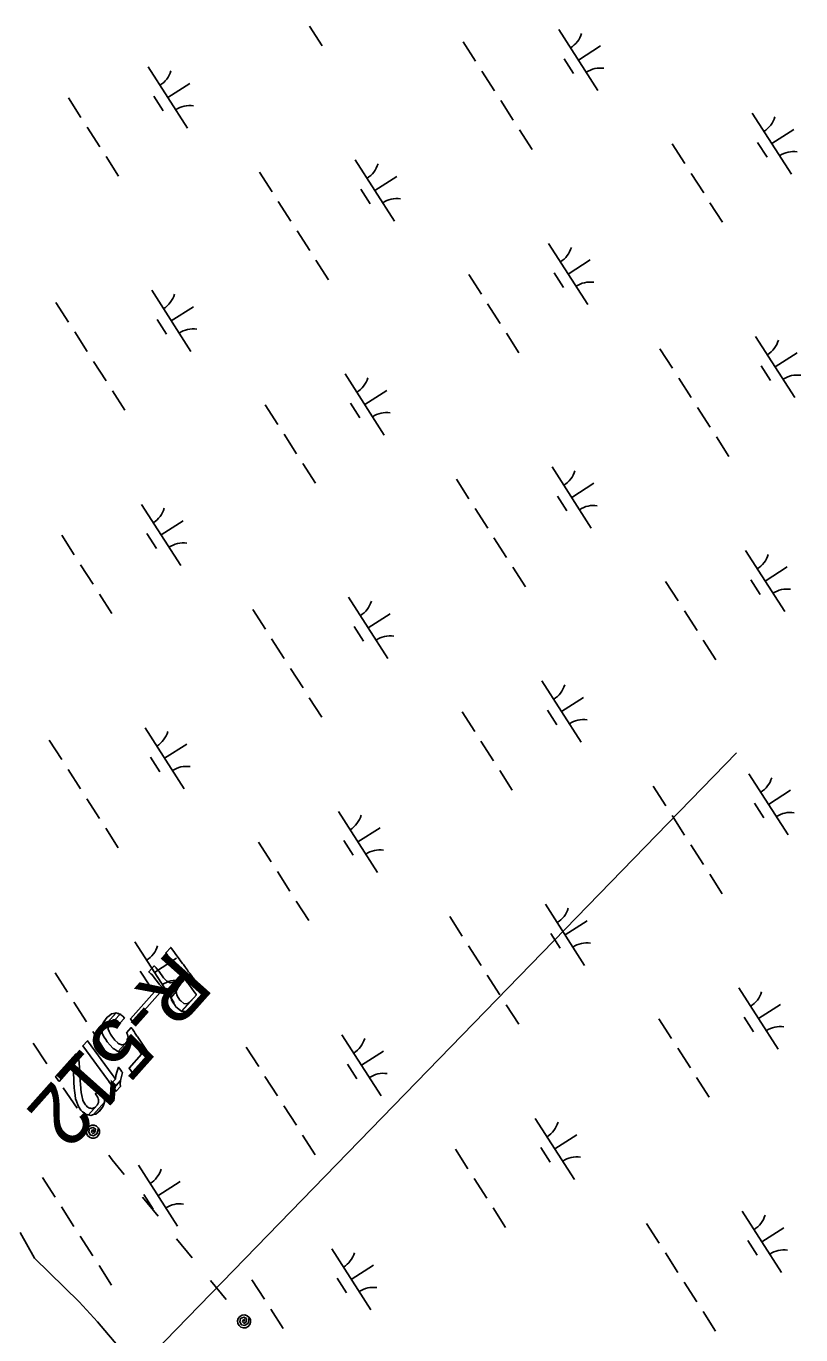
# Model space of a CAD drawing. Extents: x 3962991 to 3983549, y 181631 to 204078.
# Drawn here: x 3971703 to 3972236, y 196321 to 197222 of the extents above; entities that cross this region are included whole.
import ezdxf

# ---------------------------------------------------------------- set-up
doc = ezdxf.new("R2010")
doc.units = 0
for name, color, linetype in [('V-ANNO-MASK', 7, 'Continuous'), ('V-ANNO-MASK2', 7, 'Continuous'), ('V-RIVR-RANG-IDEN', 7, 'Continuous'), ('V-UTIL-LINE', 7, 'Continuous'), ('V-WETL-SWMP', 7, 'Continuous')]:
    doc.layers.add(name, color=color, linetype=linetype)

msp = doc.modelspace()

# ---------------------------------------------------------------- linework, layer by layer
at = {"layer": 'V-ANNO-MASK2'}
for points in [[(3971803.82, 196586.27), (3971802.63, 196587.89), (3971799.21, 196584.05), (3971800.4, 196582.43), (3971800.65, 196582.09), (3971801.86, 196580.45), (3971802.22, 196579.95), (3971805.42, 196575.6), (3971805.82, 196575.04), (3971807.31, 196573.01), (3971807.93, 196572.18), (3971808.91, 196570.84), (3971809.62, 196569.87), (3971809.84, 196569.57), (3971810.03, 196569.31), (3971800.66, 196558.81), (3971802.29, 196558.9), (3971804.9, 196560.35), (3971803.74, 196558.52), (3971802.64, 196555.42), (3971802.7, 196555.05), (3971812.46, 196566), (3971812.58, 196565.84), (3971813.21, 196564.98), (3971814.25, 196563.56), (3971814.59, 196563.11), (3971816.67, 196560.27), (3971817.22, 196559.52), (3971818.77, 196557.41), (3971819.91, 196555.87), (3971820.14, 196555.54), (3971820.14, 196555.55), (3971820.24, 196555.41), (3971820.28, 196555.34), (3971810.21, 196544.05), (3971813.84, 196543.83), (3971817.17, 196545.69), (3971820.25, 196548.88), (3971826.29, 196555.65), (3971826.18, 196555.8), (3971825.43, 196556.83), (3971823.7, 196559.18), (3971823.66, 196559.24), (3971823.56, 196559.37), (3971823.32, 196559.7), (3971822.19, 196561.24), (3971820.64, 196563.35), (3971820.09, 196564.1), (3971818.01, 196566.94), (3971817.67, 196567.4), (3971816.63, 196568.82), (3971816, 196569.68), (3971815.88, 196569.83), (3971815.71, 196570.07), (3971814.96, 196571.1), (3971814.74, 196571.39), (3971814.15, 196572.2), (3971813.45, 196573.15), (3971813.26, 196573.41), (3971813.04, 196573.71), (3971812.33, 196574.68), (3971811.35, 196576.01), (3971810.74, 196576.85), (3971809.24, 196578.88), (3971808.84, 196579.43), (3971805.65, 196583.79), (3971805.28, 196584.29), (3971804.07, 196585.93)], [(3971792.64, 196573.73), (3971791.27, 196575.15), (3971787.54, 196570.97), (3971789.04, 196569.7), (3971789.33, 196569.4), (3971790.7, 196567.93), (3971791.07, 196567.45), (3971794.33, 196563.17), (3971794.74, 196562.62), (3971796.45, 196560.83), (3971797.15, 196560.09), (3971798.63, 196559.31), (3971799.69, 196558.75), (3971800.21, 196558.78), (3971800.66, 196558.81), (3971806.8, 196565.69), (3971804.78, 196563.9), (3971804.19, 196563.79), (3971802.3, 196563.43), (3971800.81, 196564.19), (3971799.86, 196564.66), (3971798.22, 196566.52), (3971797.77, 196567.02), (3971794.57, 196571.37), (3971794.19, 196571.85), (3971792.92, 196573.43)], [(3971795.27, 196556.79), (3971793.37, 196559.38), (3971774.85, 196538.62), (3971776.75, 196536.03)], [(3971807.52, 196560.17), (3971809.66, 196562.85), (3971802.7, 196555.05), (3971802.74, 196554.81), (3971802.94, 196553.47), (3971806.48, 196557.44)], [(3971806.88, 196555.3), (3971806.47, 196557.43), (3971802.94, 196553.47), (3971803.27, 196551.25), (3971803.59, 196550.77), (3971805.58, 196547.84), (3971806.11, 196547.06), (3971808.13, 196545.48), (3971809.61, 196544.32), (3971809.91, 196544.07), (3971810.12, 196544.06), (3971815.76, 196550.39), (3971815.21, 196550.01), (3971813.9, 196549.13), (3971811.58, 196549.34), (3971809.65, 196551.03), (3971808.96, 196551.62), (3971807.01, 196554.61)], [(3971817.52, 196552.24), (3971815.76, 196550.38), (3971810.12, 196544.06), (3971810.21, 196544.05)], [(3971759.96, 196540.64), (3971758.98, 196539.91), (3971756.5, 196536.77), (3971756.02, 196535.49), (3971755.06, 196532.97), (3971755.2, 196531.75), (3971765.09, 196542.83), (3971763.56, 196542.5), (3971761.96, 196542.15)], [(3971766.35, 196542.43), (3971765.08, 196542.82), (3971755.2, 196531.75), (3971755.39, 196530.14), (3971761.1, 196536.55), (3971762.81, 196537.76), (3971763.13, 196537.99), (3971764.11, 196537.97), (3971764.12, 196537.98), (3971764.23, 196537.98), (3971767.8, 196541.97), (3971767.7, 196542), (3971766.93, 196542.24), (3971766.84, 196542.28)], [(3971759.67, 196534.24), (3971761.1, 196536.55), (3971755.39, 196530.14), (3971755.46, 196529.52), (3971755.47, 196529.4), (3971755.58, 196528.41), (3971755.63, 196528.33), (3971755.94, 196527.82), (3971756.04, 196527.66), (3971756.91, 196526.21), (3971756.95, 196526.15), (3971757.96, 196524.48), (3971758.87, 196522.97), (3971760.94, 196520.62), (3971762.84, 196518.47), (3971762.97, 196518.31), (3971763.51, 196518.01), (3971763.94, 196517.75), (3971765.35, 196516.92), (3971765.65, 196516.75), (3971766.4, 196516.31), (3971766.4, 196516.32), (3971766.56, 196516.22), (3971771.32, 196521.55), (3971770.93, 196521.4), (3971769.21, 196520.74), (3971768.87, 196520.86), (3971767.23, 196521.44), (3971766.72, 196521.61), (3971766.29, 196522.03), (3971766.14, 196522.17), (3971764.08, 196524.15), (3971762.21, 196526.71), (3971761.18, 196528.1), (3971760.31, 196529.91), (3971760.27, 196529.98), (3971759.51, 196531.55), (3971759.53, 196531.85), (3971759.58, 196532.76), (3971759.59, 196532.91), (3971759.66, 196534.1)], [(3971768.25, 196541.63), (3971767.79, 196541.97), (3971764.23, 196537.98), (3971764.98, 196537.96), (3971765.14, 196537.86), (3971766.53, 196537), (3971766.58, 196536.95), (3971767.69, 196535.83), (3971770.78, 196539.29), (3971769.74, 196540.49), (3971769.68, 196540.54), (3971768.4, 196541.51)], [(3971775.62, 196532.49), (3971775.5, 196532.66), (3971772.28, 196529.05), (3971772.39, 196528.87), (3971772.7, 196528.31), (3971772.96, 196527.86), (3971773.34, 196525.87), (3971773.19, 196525.19), (3971773.19, 196525.2), (3971772.82, 196523.52), (3971771.31, 196521.54), (3971766.57, 196516.22), (3971766.86, 196516.04), (3971767.99, 196516.08), (3971775.63, 196524.65), (3971776.41, 196523.52), (3971776.71, 196523.08), (3971776.93, 196522.74), (3971782.57, 196514.5), (3971773.94, 196504.82), (3971776.36, 196501.54), (3971787.91, 196514.49), (3971785.59, 196517.89), (3971779.96, 196526.13), (3971779.73, 196526.46), (3971779.43, 196526.9), (3971778.65, 196528.04), (3971778.18, 196528.73), (3971777.98, 196529.02), (3971777.87, 196529.18), (3971777.39, 196529.9), (3971777.19, 196530.19), (3971776.25, 196531.55), (3971775.97, 196531.97)], [(3971762.36, 196500.47), (3971745.34, 196523.66), (3971742.13, 196520.05), (3971759.15, 196496.87), (3971759.79, 196496), (3971760.61, 196494.9), (3971761.47, 196493.71), (3971764.68, 196497.31), (3971763.82, 196498.49), (3971763, 196499.6)], [(3971775.56, 196522.56), (3971775.63, 196524.65), (3971767.99, 196516.08), (3971769.84, 196516.15), (3971770.55, 196516.17), (3971771.92, 196517.12), (3971773.2, 196518.01), (3971773.2, 196518.01), (3971774.92, 196520.48), (3971775.2, 196521.38)], [(3971739.44, 196511.63), (3971737.31, 196514.54), (3971723.38, 196498.92), (3971725.51, 196496.02), (3971725.77, 196495.67), (3971735.61, 196506.7), (3971735.8, 196500.68), (3971735.91, 196497.65), (3971736.01, 196495.16), (3971736.28, 196491.31), (3971736.41, 196489.34), (3971736.88, 196486.11), (3971737.22, 196483.72), (3971737.79, 196482.03), (3971738.86, 196478.82), (3971738.87, 196478.78), (3971740.37, 196476.62), (3971740.86, 196475.93), (3971741.43, 196475.1), (3971742.01, 196474.69), (3971742.37, 196474.43), (3971743.04, 196473.95), (3971743.61, 196473.55), (3971744, 196473.27), (3971744.44, 196472.95), (3971744.97, 196472.85), (3971745.47, 196472.75), (3971745.87, 196472.67), (3971745.98, 196472.64), (3971746.05, 196472.63), (3971751.93, 196479.22), (3971751.36, 196478.68), (3971750.46, 196477.81), (3971749.69, 196477.48), (3971748.72, 196477.05), (3971748.14, 196477.11), (3971747.48, 196477.17), (3971746.88, 196477.22), (3971746.27, 196477.57), (3971745.54, 196477.98), (3971745.14, 196478.2), (3971744.68, 196478.74), (3971744.03, 196479.49), (3971743.48, 196480.12), (3971742.28, 196482.61), (3971742.26, 196482.64), (3971741.38, 196486.06), (3971741.11, 196488.07), (3971740.77, 196490.48), (3971740.5, 196493.93), (3971740.35, 196495.88), (3971740.1, 196499.75), (3971739.94, 196502.17), (3971739.79, 196505.15), (3971739.47, 196511.03)], [(3971767.42, 196504.56), (3971766.78, 196505.43), (3971765.75, 196502.68), (3971764.96, 196499.78), (3971764.68, 196497.31), (3971761.47, 196493.71), (3971761.9, 196493.12), (3971762.58, 196492.2), (3971763.43, 196491.04), (3971768.14, 196496.32), (3971768.72, 196499.08), (3971769.53, 196501.68), (3971769.1, 196502.27), (3971768.24, 196503.45)], [(3971767.9, 196493.83), (3971768.14, 196496.31), (3971763.43, 196491.04), (3971764.32, 196489.83), (3971765.03, 196488.86), (3971768.03, 196492.22)], [(3971754.69, 196489.96), (3971754.12, 196490.8), (3971750.88, 196487.16), (3971751.45, 196486.33), (3971751.86, 196485.73), (3971752.11, 196485.35), (3971752.44, 196484.5), (3971752.72, 196483.77), (3971752.91, 196483.27), (3971752.91, 196482.45), (3971752.91, 196481.75), (3971752.91, 196481.09), (3971752.24, 196479.81), (3971752.05, 196479.44), (3971751.93, 196479.21), (3971746.05, 196472.63), (3971747.68, 196472.3), (3971749.57, 196472.81), (3971757.18, 196481.34), (3971757.14, 196482.9), (3971757.07, 196484.99), (3971757.07, 196485.07), (3971757.03, 196485.18), (3971756.89, 196485.55), (3971756.71, 196486.01), (3971756.52, 196486.49), (3971756.3, 196487.06), (3971756.1, 196487.56), (3971755.82, 196488.28), (3971755.35, 196488.98), (3971755.1, 196489.36)], [(3971756.38, 196479.22), (3971757.18, 196481.34), (3971749.57, 196472.81), (3971751.01, 196473.2), (3971752.93, 196474.72), (3971755.97, 196478.14)], [(3971753.8, 196475.41), (3971755.97, 196478.14), (3971752.93, 196474.72), (3971753.79, 196475.41)]]:
    msp.add_lwpolyline(points, close=True, dxfattribs=at)
at = {"layer": 'V-UTIL-LINE'}
msp.add_line((3972191.85, 196721.9), (3970928.71, 195421.26), dxfattribs=at)
for points in [[(3971707.91, 196521.91), (3971717.45, 196507.84)], [(3971728.67, 196491.28), (3971738.21, 196477.21)], [(3971749.17, 196461.05), (3971749.69, 196462.39), (3971748.56, 196462.12), (3971748.09, 196460.82), (3971749.04, 196459.71), (3971750.49, 196460.6), (3971750.99, 196462.89), (3971749.17, 196463.99), (3971746.86, 196463.21), (3971746.32, 196460.99), (3971747.14, 196458.91), (3971749.46, 196458.23), (3971751.82, 196459.64), (3971752.89, 196463.58), (3971751.64, 196464.81), (3971750.02, 196465.47), (3971748.26, 196465.46), (3971746.64, 196464.78), (3971745.41, 196463.53), (3971744.75, 196461.9), (3971744.76, 196460.14), (3971745.44, 196458.53), (3971746.69, 196457.29), (3971748.32, 196456.63), (3971750.07, 196456.64), (3971751.69, 196457.33), (3971752.93, 196458.58), (3971753.59, 196460.2), (3971753.57, 196461.96), (3971752.89, 196463.58)], [(3971760.1, 196444.93), (3971762.28, 196441.71), (3971770.57, 196431.56)], [(3971783.22, 196416.06), (3971793.97, 196402.89)], [(3971806.61, 196387.4), (3971817.36, 196374.23)], [(3971830.01, 196358.73), (3971840.76, 196345.56)], [(3971853.1, 196330.44), (3971853.5, 196331.82), (3971852.4, 196331.44), (3971852.05, 196330.12), (3971853.1, 196329.09), (3971854.46, 196330.1), (3971854.76, 196332.43), (3971852.84, 196333.37), (3971850.62, 196332.39), (3971850.27, 196330.12), (3971851.28, 196328.13), (3971853.64, 196327.66), (3971855.87, 196329.27), (3971856.59, 196333.28), (3971855.23, 196334.4), (3971853.56, 196334.92), (3971851.81, 196334.75), (3971850.26, 196333.93), (3971849.14, 196332.57), (3971848.63, 196330.89), (3971848.79, 196329.14), (3971849.62, 196327.59), (3971850.97, 196326.48), (3971852.65, 196325.96), (3971854.4, 196326.13), (3971855.95, 196326.95), (3971857.07, 196328.31), (3971857.58, 196329.99), (3971857.41, 196331.73), (3971856.59, 196333.28)]]:
    msp.add_lwpolyline(points, dxfattribs=at)
at = {"layer": 'V-WETL-SWMP'}
for p, q in [((3971898.17, 197221.88), (3971906.8, 197208.41)), ((3972069.62, 197219.64), (3972096.6, 197177.55)), ((3972003.74, 197211.16), (3972012.37, 197197.69)), ((3972083.11, 197198.59), (3972098.26, 197208.31)), ((3972073.38, 197199.48), (3972079.85, 197189.38)), ((3971787.14, 197193.82), (3971814.12, 197151.72)), ((3972016.69, 197190.96), (3972025.33, 197177.49)), ((3971800.63, 197172.77), (3971815.78, 197182.48)), ((3971732.23, 197172.52), (3971740.87, 197159.05)), ((3971790.9, 197173.66), (3971797.37, 197163.55)), ((3972029.64, 197170.76), (3972038.28, 197157.29)), ((3972202.64, 197162.1), (3972229.63, 197120)), ((3971745.18, 197152.32), (3971753.82, 197138.85)), ((3972042.6, 197150.55), (3972051.23, 197137.08)), ((3972216.13, 197141.05), (3972231.29, 197150.77)), ((3972147.74, 197140.8), (3972156.37, 197127.33)), ((3972206.4, 197141.94), (3972212.88, 197131.84)), ((3971758.14, 197132.11), (3971766.77, 197118.64)), ((3971929.59, 197129.87), (3971956.57, 197087.77)), ((3971863.71, 197121.39), (3971872.34, 197107.92)), ((3971943.08, 197108.82), (3971958.23, 197118.53)), ((3972160.69, 197120.6), (3972169.32, 197107.13)), ((3971933.35, 197109.71), (3971939.82, 197099.6)), ((3971876.66, 197101.19), (3971885.29, 197087.72)), ((3972173.64, 197100.39), (3972182.28, 197086.92)), ((3971889.61, 197080.98), (3971898.25, 197067.51)), ((3972062.61, 197072.32), (3972089.6, 197030.23)), ((3971902.56, 197060.78), (3971911.2, 197047.31)), ((3972076.1, 197051.28), (3972091.26, 197060.99)), ((3972007.7, 197051.03), (3972016.34, 197037.56)), ((3972066.37, 197052.16), (3972072.85, 197042.06)), ((3971789.55, 197040.09), (3971816.54, 196998)), ((3971723.67, 197031.62), (3971732.31, 197018.15)), ((3971803.05, 197019.05), (3971818.2, 197028.76)), ((3972020.66, 197030.82), (3972029.29, 197017.35)), ((3971793.31, 197019.93), (3971799.79, 197009.83)), ((3971736.63, 197011.41), (3971745.26, 196997.94)), ((3972033.61, 197010.62), (3972042.25, 196997.15)), ((3972205.06, 197008.37), (3972232.04, 196966.28)), ((3972139.18, 196999.9), (3972147.81, 196986.43)), ((3972218.55, 196987.33), (3972233.71, 196997.04)), ((3971749.58, 196991.21), (3971758.21, 196977.74)), ((3972208.82, 196988.21), (3972215.29, 196978.11)), ((3971922.58, 196982.55), (3971949.56, 196940.46)), ((3972152.13, 196979.69), (3972160.77, 196966.22)), ((3971762.53, 196971), (3971771.17, 196957.53)), ((3971936.07, 196961.5), (3971951.22, 196971.22)), ((3971867.67, 196961.25), (3971876.31, 196947.78)), ((3971926.34, 196962.39), (3971932.81, 196952.29)), ((3972165.08, 196959.49), (3972173.72, 196946.02)), ((3971880.63, 196941.05), (3971889.26, 196927.58)), ((3972178.04, 196939.28), (3972186.67, 196925.82)), ((3971893.58, 196920.84), (3971902.21, 196907.37)), ((3972065.03, 196918.6), (3972092.01, 196876.51)), ((3971999.15, 196910.12), (3972007.78, 196896.65)), ((3972078.52, 196897.55), (3972093.67, 196907.27)), ((3972068.79, 196898.44), (3972075.26, 196888.34)), ((3971782.55, 196892.78), (3971809.53, 196850.68)), ((3972012.1, 196889.92), (3972020.74, 196876.45)), ((3971796.04, 196871.73), (3971811.19, 196881.44)), ((3971727.64, 196871.48), (3971736.28, 196858.01)), ((3971786.31, 196872.62), (3971792.78, 196862.51)), ((3972025.05, 196869.72), (3972033.69, 196856.25)), ((3972198.05, 196861.06), (3972225.04, 196818.96)), ((3971740.59, 196851.28), (3971749.23, 196837.81)), ((3972038.01, 196849.51), (3972046.64, 196836.04)), ((3972211.54, 196840.01), (3972226.7, 196849.73)), ((3972143.15, 196839.76), (3972151.78, 196826.29)), ((3972201.81, 196840.9), (3972208.29, 196830.8)), ((3971753.55, 196831.07), (3971762.18, 196817.6)), ((3971925, 196828.83), (3971951.98, 196786.73)), ((3971859.12, 196820.35), (3971867.75, 196806.88)), ((3971938.49, 196807.78), (3971953.64, 196817.49)), ((3972156.1, 196819.56), (3972164.73, 196806.09)), ((3971928.75, 196808.67), (3971935.23, 196798.56)), ((3971872.07, 196800.15), (3971880.7, 196786.68)), ((3972169.05, 196799.35), (3972177.69, 196785.88)), ((3971885.02, 196779.94), (3971893.66, 196766.47)), ((3972058.02, 196771.28), (3972085.01, 196729.19)), ((3971897.97, 196759.74), (3971906.61, 196746.27)), ((3972071.51, 196750.24), (3972086.67, 196759.95)), ((3972003.11, 196749.99), (3972011.75, 196736.52)), ((3972061.78, 196751.12), (3972068.26, 196741.02)), ((3971784.96, 196739.05), (3971811.95, 196696.96)), ((3971719.08, 196730.58), (3971727.72, 196717.11)), ((3971798.46, 196718.01), (3971813.61, 196727.72)), ((3972016.07, 196729.78), (3972024.7, 196716.31)), ((3971788.72, 196718.89), (3971795.2, 196708.79)), ((3971732.04, 196710.37), (3971740.67, 196696.9)), ((3972029.02, 196709.58), (3972037.66, 196696.11)), ((3972134.59, 196698.86), (3972143.22, 196685.39)), ((3972200.47, 196707.33), (3972227.45, 196665.24)), ((3971744.99, 196690.17), (3971753.62, 196676.7)), ((3972213.96, 196686.29), (3972229.12, 196696)), ((3971917.99, 196681.51), (3971944.97, 196639.42)), ((3972204.23, 196687.17), (3972210.7, 196677.07)), ((3972147.54, 196678.65), (3972156.18, 196665.18)), ((3971757.94, 196669.96), (3971766.58, 196656.49)), ((3971931.48, 196660.46), (3971946.63, 196670.18)), ((3971863.08, 196660.21), (3971871.72, 196646.74)), ((3971921.75, 196661.35), (3971928.22, 196651.25)), ((3972160.49, 196658.45), (3972169.13, 196644.98)), ((3971876.04, 196640.01), (3971884.67, 196626.54)), ((3972173.45, 196638.24), (3972182.08, 196624.78)), ((3971888.99, 196619.8), (3971897.62, 196606.33)), ((3972060.44, 196617.56), (3972087.42, 196575.47)), ((3971994.56, 196609.08), (3972003.19, 196595.62)), ((3972073.93, 196596.51), (3972089.08, 196606.23)), ((3971777.96, 196591.74), (3971804.94, 196549.64)), ((3972064.2, 196597.4), (3972070.67, 196587.3)), ((3972007.51, 196588.88), (3972016.15, 196575.41)), ((3971791.45, 196570.69), (3971806.6, 196580.4)), ((3971723.05, 196570.44), (3971731.69, 196556.97)), ((3971781.72, 196571.58), (3971788.19, 196561.47)), ((3972020.46, 196568.68), (3972029.1, 196555.21)), ((3972193.46, 196560.02), (3972220.45, 196517.92)), ((3971736, 196550.24), (3971744.64, 196536.77)), ((3972033.42, 196548.47), (3972042.05, 196535)), ((3972206.95, 196538.97), (3972222.11, 196548.69)), ((3972138.56, 196538.72), (3972147.19, 196525.25)), ((3972197.22, 196539.86), (3972203.7, 196529.76)), ((3971748.96, 196530.03), (3971757.59, 196516.56)), ((3971920.41, 196527.79), (3971947.39, 196485.69)), ((3971854.53, 196519.31), (3971863.16, 196505.84)), ((3972151.51, 196518.52), (3972160.14, 196505.05)), ((3971933.9, 196506.74), (3971949.05, 196516.45)), ((3971924.16, 196507.63), (3971930.64, 196497.52)), ((3971867.48, 196499.11), (3971876.11, 196485.64)), ((3972164.46, 196498.31), (3972173.1, 196484.84)), ((3971880.43, 196478.9), (3971889.07, 196465.43)), ((3972053.43, 196470.24), (3972080.42, 196428.15)), ((3971893.38, 196458.7), (3971902.02, 196445.23)), ((3972066.92, 196449.2), (3972082.08, 196458.91)), ((3971998.52, 196448.95), (3972007.16, 196435.48)), ((3972057.19, 196450.08), (3972063.67, 196439.98)), ((3971780.37, 196438.01), (3971807.36, 196395.92)), ((3971714.49, 196429.54), (3971723.13, 196416.07)), ((3972011.48, 196428.74), (3972020.11, 196415.27)), ((3971793.87, 196416.97), (3971809.02, 196426.68)), ((3971784.13, 196417.85), (3971790.61, 196407.75)), ((3971727.45, 196409.33), (3971736.08, 196395.86)), ((3972024.43, 196408.54), (3972033.07, 196395.07)), ((3972195.88, 196406.29), (3972222.86, 196364.2)), ((3972130, 196397.82), (3972138.63, 196384.35)), ((3972209.37, 196385.25), (3972224.53, 196394.96)), ((3971708.81, 196373.94), (3971699.04, 196391.75)), ((3971740.4, 196389.13), (3971749.03, 196375.66)), ((3972199.64, 196386.13), (3972206.11, 196376.03)), ((3971913.4, 196380.47), (3971940.38, 196338.38)), ((3972142.95, 196377.61), (3972151.59, 196364.14)), ((3971739.61, 196343.85), (3971708.81, 196373.94)), ((3971753.35, 196368.92), (3971761.99, 196355.45)), ((3971926.89, 196359.42), (3971942.04, 196369.14)), ((3971858.49, 196359.17), (3971867.13, 196345.7)), ((3971917.16, 196360.31), (3971923.63, 196350.21)), ((3972155.9, 196357.41), (3972164.54, 196343.94)), ((3971752.31, 196330.26), (3971739.61, 196343.85)), ((3971871.45, 196338.97), (3971880.08, 196325.5)), ((3971768.66, 196310.74), (3971752.31, 196330.26)), ((3972168.86, 196337.2), (3972177.49, 196323.74))]:
    msp.add_line(p, q, dxfattribs=at)
for centre, start, end in [((3972068.4, 197221.97), 301.89187, 343.43553), ((3971785.92, 197196.15), 301.89187, 343.43553), ((3972098.22, 197175.47), 81.89186, 123.43552), ((3971815.74, 197149.64), 81.89186, 123.43552), ((3972201.43, 197164.43), 301.89187, 343.43553), ((3972231.24, 197117.93), 81.89186, 123.43552), ((3971928.37, 197132.2), 301.89187, 343.43553), ((3971958.19, 197085.69), 81.89186, 123.43552), ((3972061.4, 197074.66), 301.89187, 343.43553), ((3972091.21, 197028.15), 81.89186, 123.43552), ((3971788.34, 197042.43), 301.89187, 343.43553), ((3971818.15, 196995.92), 81.89186, 123.43552), ((3972203.84, 197010.71), 301.89187, 343.43553), ((3971921.36, 196984.88), 301.89187, 343.43553), ((3972233.66, 196964.2), 81.89186, 123.43552), ((3971951.18, 196938.38), 81.89186, 123.43552), ((3972063.81, 196920.93), 301.89187, 343.43553), ((3971781.33, 196895.11), 301.89187, 343.43553), ((3972093.63, 196874.43), 81.89186, 123.43552), ((3971811.15, 196848.6), 81.89186, 123.43552), ((3972196.84, 196863.39), 301.89187, 343.43553), ((3972226.65, 196816.89), 81.89186, 123.43552), ((3971923.78, 196831.16), 301.89187, 343.43553), ((3971953.6, 196784.65), 81.89186, 123.43552), ((3972056.81, 196773.62), 301.89187, 343.43553), ((3972086.62, 196727.11), 81.89186, 123.43552), ((3971783.75, 196741.39), 301.89187, 343.43553), ((3971813.56, 196694.88), 81.89186, 123.43552), ((3972199.25, 196709.67), 301.89187, 343.43553), ((3972229.07, 196663.16), 81.89186, 123.43552), ((3971916.77, 196683.85), 301.89187, 343.43553), ((3971946.59, 196637.34), 81.89186, 123.43552), ((3972059.22, 196619.89), 301.89187, 343.43553), ((3972089.04, 196573.39), 81.89186, 123.43552), ((3971776.74, 196594.07), 301.89187, 343.43553), ((3971806.56, 196547.57), 81.89186, 123.43552), ((3972192.25, 196562.35), 301.89187, 343.43553), ((3972222.06, 196515.85), 81.89186, 123.43552), ((3971919.19, 196530.12), 301.89187, 343.43553), ((3971949.01, 196483.61), 81.89186, 123.43552), ((3972052.21, 196472.58), 301.89187, 343.43553), ((3972082.03, 196426.07), 81.89186, 123.43552), ((3971779.16, 196440.35), 301.89187, 343.43553), ((3971808.97, 196393.84), 81.89186, 123.43552), ((3972194.66, 196408.63), 301.89187, 343.43553), ((3971912.18, 196382.81), 301.89187, 343.43553), ((3972224.48, 196362.12), 81.89186, 123.43552), ((3971942, 196336.3), 81.89186, 123.43552)]:
    msp.add_arc(centre, 17.62, start, end, dxfattribs=at)

# ---------------------------------------------------------------- texts
at = {"layer": 'V-ANNO-MASK'}
msp.add_text('R-512  ', height=41.5, rotation=228.26932, dxfattribs=at).set_placement((3971802.21, 196587.42))
at = {"layer": 'V-RIVR-RANG-IDEN'}
msp.add_text('R-512  ', height=41.5, rotation=228.26932, dxfattribs=at).set_placement((3971802.21, 196587.42))

doc.saveas('drawing.dxf')
